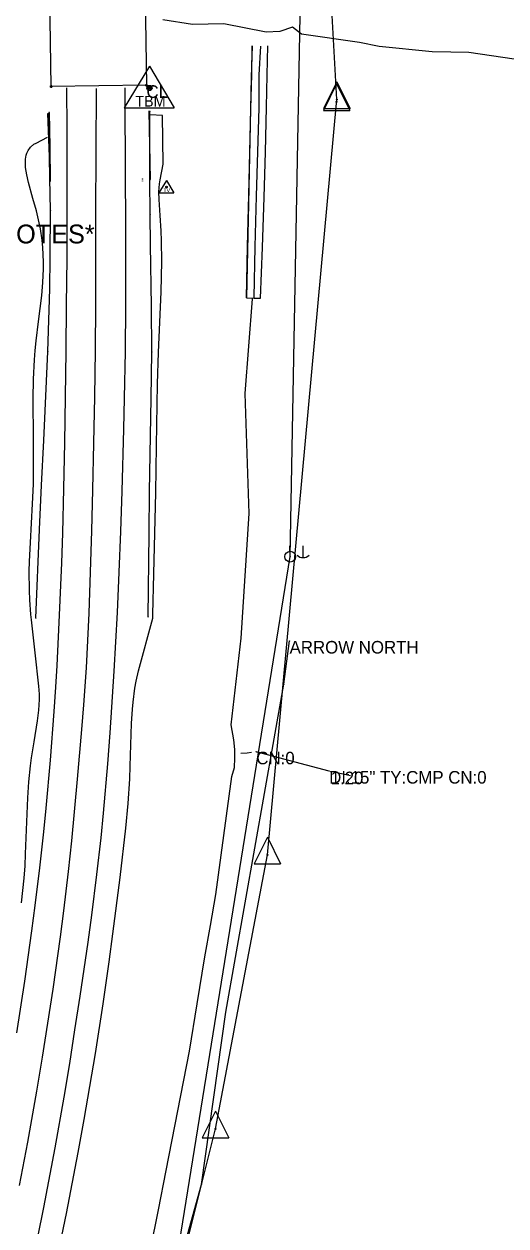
# Model space of a CAD drawing. Extents: x 1674300 to 1677920, y 225056 to 231852.
# Drawn here: x 1677431.2 to 1677622.7, y 228668.9 to 229147 of the extents above; entities that cross this region are included whole.
import ezdxf

# ---------------------------------------------------------------- set-up
doc = ezdxf.new("R2010")
doc.units = 0
for name, color, linetype in [('S_BRIDGE', 7, 'Continuous'), ('S_BRIDGE_ANNOT', 7, 'Continuous'), ('S_CAL_CORNER_ANNOT', 7, 'Continuous'), ('S_CURB', 7, 'Continuous'), ('S_DITCHLINE', 7, 'Continuous'), ('S_DRG_PT_SYM', 7, 'Continuous'), ('S_DROP_INLET_ANNOT', 7, 'Continuous'), ('S_EDGE_CONCRETE', 7, 'Continuous'), ('S_EDGE_PAVEMENT', 7, 'Continuous'), ('S_ELECTRIC_UTILITIES', 7, 'Continuous'), ('S_EXIST_ROW', 7, 'Continuous'), ('S_FIBER_OPTIC_CABLE', 7, 'Continuous'), ('S_FIBER_OPTIC_CABLE_ANNOT', 7, 'Continuous'), ('S_GUARDRAIL', 7, 'Continuous'), ('S_MSC_PT_SYM', 7, 'Continuous'), ('S_PAVEMENT_CROWN', 7, 'Continuous'), ('S_PRIMARY_CTL', 7, 'Continuous'), ('S_RDW_PT_SYM', 7, 'Continuous'), ('S_SECONDARY_CTL', 7, 'Continuous'), ('S_SHOULDER', 7, 'Continuous'), ('S_SIDE_DRAIN', 7, 'Continuous'), ('S_SIDE_DRAIN_ANNOT', 7, 'Continuous'), ('S_STR_PT_SYM', 7, 'Continuous'), ('S_STREAM', 7, 'Continuous'), ('S_UTILITY_POLE', 7, 'Continuous'), ('S_UTL_PT_SYM', 7, 'Continuous')]:
    doc.layers.add(name, color=color, linetype=linetype)

msp = doc.modelspace()

# ---------------------------------------------------------------- linework, layer by layer
at = {"layer": 'S_BRIDGE'}
for p, q in [((1677441.95, 229122.22), (1677441.12, 229176.97)), ((1677478.98, 229177.38), (1677479.86, 229122.68)), ((1677479.86, 229122.68), (1677441.95, 229122.22))]:
    msp.add_line(p, q, dxfattribs=at)
at = {"layer": 'S_CURB'}
msp.add_lwpolyline([(1677441.03, 229111.79), (1677441.26, 229098.22), (1677441.49, 229084.65), (1677441.72, 229084.58), (1677441.51, 229098.19), (1677441.3, 229111.8)], close=True, dxfattribs=at)
at = {"layer": 'S_DITCHLINE'}
for points in [[(1677522.63, 229038.26), (1677523.12, 229058.43), (1677523.6, 229078.59), (1677524.1, 229096.18), (1677524.6, 229113.77), (1677524.67, 229126.78), (1677525.27, 229138.2)], [(1677481.44, 228659.54), (1677484.58, 228675.24), (1677487.72, 228690.94), (1677492.32, 228714.69), (1677496.91, 228738.44), (1677499.97, 228757.22), (1677503.03, 228775.99), (1677505.25, 228788.38), (1677507.46, 228800.77), (1677510.6, 228824.19), (1677513.73, 228847.61), (1677514.83, 228851.31), (1677515.02, 228854.93), (1677514.96, 228858.41), (1677514.63, 228862.29), (1677513.48, 228868.18), (1677515.51, 228885.41), (1677517.54, 228902.65), (1677519.12, 228927.5), (1677520.71, 228952.35), (1677519.88, 228976.18), (1677519.06, 229000), (1677520.55, 229018.83), (1677522.04, 229037.67)], [(1677517.33, 228856.94), (1677519.88, 228857.15), (1677521.64, 228857.29)], [(1677561.01, 228848), (1677553.85, 228849.54)]]:
    msp.add_lwpolyline(points, dxfattribs=at)
at = {"layer": 'S_DRG_PT_SYM'}
for points in [[(1677523.52, 228857.52), (1677523.52, 228857.57), (1677523.52, 228857.52), (1677523.47, 228857.52), (1677523.52, 228857.52), (1677523.52, 228857.47), (1677523.52, 228857.52), (1677523.57, 228857.52)], [(1677552.48, 228849.85), (1677552.48, 228849.9), (1677552.48, 228849.85), (1677552.43, 228849.85), (1677552.48, 228849.85), (1677552.48, 228849.8), (1677552.48, 228849.85), (1677552.53, 228849.85)], [(1677553.05, 228849.61), (1677553.05, 228849.66), (1677553.05, 228849.61), (1677553, 228849.61), (1677553.05, 228849.61), (1677553.05, 228849.56), (1677553.05, 228849.61), (1677553.1, 228849.61)]]:
    msp.add_lwpolyline(points, dxfattribs=at)
at = {"layer": 'S_EDGE_CONCRETE'}
for points in [[(1677519.57, 229038.13), (1677520.04, 229058.54), (1677520.52, 229078.95), (1677520.93, 229096.11), (1677521.34, 229113.27), (1677521.67, 229126.86), (1677521.82, 229138.35), (1677521.53, 229125.82), (1677521.25, 229113.29), (1677520.97, 229100.76), (1677520.69, 229088.24), (1677520.41, 229075.71), (1677520.13, 229063.18), (1677519.85, 229050.65)], [(1677480.74, 229112.39), (1677481.01, 229098.81), (1677481.28, 229085.22), (1677481.44, 229085.19), (1677481.19, 229098.78), (1677480.94, 229112.36)]]:
    msp.add_lwpolyline(points, close=True, dxfattribs=at)
msp.add_lwpolyline([(1677519.58, 229038.11), (1677522.68, 229037.98), (1677525.2, 229037.96), (1677525.95, 229058.08), (1677526.69, 229078.2), (1677527.11, 229096.11), (1677527.53, 229114.03), (1677527.87, 229126.76), (1677528.09, 229138.32)], dxfattribs=at)
at = {"layer": 'S_EDGE_PAVEMENT'}
for points in [[(1677428.3, 228745.66), (1677431.48, 228766.31), (1677434.3, 228786.31), (1677435.61, 228796.33), (1677437.42, 228811.37), (1677438.99, 228825.61), (1677439.95, 228835.12), (1677441.69, 228854.14), (1677443.21, 228873.55), (1677443.86, 228883.26), (1677444.36, 228891.83), (1677445.2, 228908.97), (1677446.16, 228932.65), (1677446.57, 228944.49), (1677447.07, 228962.26), (1677447.45, 228980.47), (1677447.69, 228998.68), (1677447.94, 229016.89), (1677448.12, 229035.35), (1677448.29, 229053.8), (1677448.38, 229072.25), (1677448.38, 229088.73), (1677448.28, 229105.21), (1677448.18, 229121.69)], [(1677436.65, 228664.42), (1677439.04, 228676.26), (1677443.55, 228699.98), (1677447.09, 228720.05), (1677449.33, 228733.45), (1677451.44, 228746.87), (1677453.55, 228760.29), (1677456.69, 228781.76), (1677458.15, 228792.51), (1677460.17, 228808.65), (1677461.79, 228823.32), (1677462.77, 228833.1), (1677464.48, 228852.7), (1677465.41, 228864.99), (1677467.02, 228889.58), (1677468.3, 228912.92), (1677469.04, 228929.01), (1677469.62, 228945.1), (1677470.21, 228961.2), (1677470.9, 228985.89), (1677471.17, 228998.24), (1677471.46, 229016.76), (1677471.6, 229034.93), (1677471.6, 229053.1), (1677471.6, 229071.27), (1677471.53, 229083.86), (1677471.46, 229096.45), (1677471.39, 229109.03), (1677471.32, 229121.62)]]:
    msp.add_lwpolyline(points, dxfattribs=at)
at = {"layer": 'S_ELECTRIC_UTILITIES'}
for p, q in [((1677537.01, 228935.14), (1677541.67, 229188.26)), ((1677492.08, 228657.14), (1677537.01, 228935.14))]:
    msp.add_line(p, q, dxfattribs=at)
at = {"layer": 'S_EXIST_ROW'}
for p, q in [((1677555.5, 229117.02), (1677521.25, 229735.57)), ((1677555.45, 229123.25), (1677550.16, 229112.61)), ((1677555.52, 229124.11), (1677550.23, 229113.47)), ((1677555.45, 229123.25), (1677560.68, 229112.61)), ((1677555.52, 229124.11), (1677560.76, 229113.47)), ((1677527.92, 228816.46), (1677555.5, 229117.02)), ((1677555.43, 229116.15), (1677555.43, 229116.15)), ((1677555.5, 229117.02), (1677555.5, 229117.02)), ((1677550.16, 229112.61), (1677560.68, 229112.61)), ((1677550.23, 229113.47), (1677560.76, 229113.47)), ((1677527.94, 228823.55), (1677522.65, 228812.91)), ((1677527.94, 228823.55), (1677533.17, 228812.91)), ((1677507.28, 228707.44), (1677527.92, 228816.46)), ((1677527.92, 228816.46), (1677527.92, 228816.46)), ((1677522.65, 228812.91), (1677533.17, 228812.91)), ((1677507.3, 228714.54), (1677502.01, 228703.9)), ((1677507.3, 228714.54), (1677512.53, 228703.9)), ((1677453.53, 228492.88), (1677507.28, 228707.44)), ((1677507.28, 228707.44), (1677507.28, 228707.44)), ((1677502.01, 228703.9), (1677512.53, 228703.9))]:
    msp.add_line(p, q, dxfattribs=at)
for centre, radius in [((1677555.43, 229116.15), 0.18), ((1677555.5, 229117.02), 0.18), ((1677555.43, 229116.15), 0.09), ((1677555.5, 229117.02), 0.09), ((1677527.92, 228816.46), 0.18), ((1677527.92, 228816.46), 0.09), ((1677507.28, 228707.44), 0.18), ((1677507.28, 228707.44), 0.09)]:
    msp.add_circle(centre, radius, dxfattribs=at)
at = {"layer": 'S_FIBER_OPTIC_CABLE'}
for p, q in [((1677534.42, 228884.38), (1677536.75, 228901.6)), ((1677511.42, 228753.9), (1677534.42, 228884.38)), ((1677501.74, 228685.3), (1677511.42, 228753.9)), ((1677487.34, 228633.72), (1677501.74, 228685.3))]:
    msp.add_line(p, q, dxfattribs=at)
at = {"layer": 'S_GUARDRAIL'}
for p, q in [((1677441.28, 229094.28), (1677440.67, 229111.44)), ((1677481.21, 229085), (1677481.23, 229112.34)), ((1677441.49, 229085.7), (1677441.28, 229094.28)), ((1677441.66, 229072.83), (1677441.49, 229085.7)), ((1677481.3, 229071.32), (1677481.21, 229085)), ((1677441.63, 229054.13), (1677441.66, 229072.83)), ((1677481.45, 229059.15), (1677481.3, 229071.32)), ((1677481.81, 229034.81), (1677481.45, 229059.15)), ((1677441.44, 229041.66), (1677441.63, 229054.13)), ((1677441.24, 229033.35), (1677441.44, 229041.66)), ((1677481.93, 229016.55), (1677481.81, 229034.81)), ((1677440.69, 229016.73), (1677441.24, 229033.35)), ((1677440.18, 229004.92), (1677440.69, 229016.73)), ((1677481.78, 228998.05), (1677481.93, 229016.55)), ((1677439.02, 228981.3), (1677440.18, 229004.92)), ((1677481.09, 228961.05), (1677481.78, 228998.05)), ((1677438.13, 228963.59), (1677439.02, 228981.3)), ((1677437.33, 228945.95), (1677438.13, 228963.59)), ((1677480.86, 228944.41), (1677481.09, 228961.05)), ((1677435.91, 228910.66), (1677437.33, 228945.95)), ((1677480.54, 228911.14), (1677480.86, 228944.41))]:
    msp.add_line(p, q, dxfattribs=at)
at = {"layer": 'S_MSC_PT_SYM'}
for points in [[(1677535.79, 229145.03), (1677535.79, 229145.08), (1677535.79, 229145.03), (1677535.74, 229145.03), (1677535.79, 229145.03), (1677535.79, 229144.98), (1677535.79, 229145.03), (1677535.84, 229145.03)], [(1677478.28, 229084.57), (1677478.28, 229084.62), (1677478.28, 229084.57), (1677478.23, 229084.57), (1677478.28, 229084.57), (1677478.28, 229084.52), (1677478.28, 229084.57), (1677478.33, 229084.57)], [(1677478.29, 229085.42), (1677478.29, 229085.47), (1677478.29, 229085.42), (1677478.24, 229085.42), (1677478.29, 229085.42), (1677478.29, 229085.37), (1677478.29, 229085.42), (1677478.34, 229085.42)]]:
    msp.add_lwpolyline(points, dxfattribs=at)
at = {"layer": 'S_PAVEMENT_CROWN'}
msp.add_lwpolyline([(1677429.34, 228684.91), (1677432.69, 228702.16), (1677436.31, 228722.44), (1677438.56, 228735.98), (1677440.65, 228749.55), (1677442.74, 228763.12), (1677445.66, 228783.88), (1677447.01, 228794.27), (1677448.87, 228809.88), (1677450.17, 228822.13), (1677452.49, 228846.67), (1677454.21, 228866.32), (1677454.98, 228876.16), (1677455.99, 228890.92), (1677457.05, 228912.6), (1677457.66, 228928.98), (1677458.11, 228945.37), (1677458.57, 228961.75), (1677458.95, 228980.23), (1677459.33, 228998.7), (1677459.56, 229017.18), (1677459.66, 229035.28), (1677459.68, 229053.38), (1677459.71, 229071.47), (1677459.84, 229096.45), (1677459.96, 229121.43)], dxfattribs=at)
at = {"layer": 'S_PRIMARY_CTL'}
for p, q in [((1677481.03, 229130.28), (1677470.99, 229113.77)), ((1677481.03, 229130.28), (1677490.85, 229113.77)), ((1677470.99, 229113.77), (1677490.85, 229113.77))]:
    msp.add_line(p, q, dxfattribs=at)
for radius in [1.04, 0.609, 0.344]:
    msp.add_circle((1677481.03, 229121.58), radius, dxfattribs=at)
at = {"layer": 'S_RDW_PT_SYM'}
for points in [[(1677440.67, 229111.44), (1677440.67, 229111.49), (1677440.67, 229111.44), (1677440.62, 229111.44), (1677440.67, 229111.44), (1677440.67, 229111.39), (1677440.67, 229111.44), (1677440.72, 229111.44)], [(1677481.23, 229112.34), (1677481.23, 229112.39), (1677481.23, 229112.34), (1677481.18, 229112.34), (1677481.23, 229112.34), (1677481.23, 229112.29), (1677481.23, 229112.34), (1677481.28, 229112.34)], [(1677441.66, 229072.83), (1677441.66, 229072.88), (1677441.66, 229072.83), (1677441.61, 229072.83), (1677441.66, 229072.83), (1677441.66, 229072.78), (1677441.66, 229072.83), (1677441.71, 229072.83)], [(1677481.3, 229071.32), (1677481.3, 229071.37), (1677481.3, 229071.32), (1677481.25, 229071.32), (1677481.3, 229071.32), (1677481.3, 229071.27), (1677481.3, 229071.32), (1677481.35, 229071.32)], [(1677440.69, 229016.73), (1677440.69, 229016.78), (1677440.69, 229016.73), (1677440.64, 229016.73), (1677440.69, 229016.73), (1677440.69, 229016.68), (1677440.69, 229016.73), (1677440.74, 229016.73)], [(1677481.93, 229016.55), (1677481.93, 229016.6), (1677481.93, 229016.55), (1677481.88, 229016.55), (1677481.93, 229016.55), (1677481.93, 229016.5), (1677481.93, 229016.55), (1677481.98, 229016.55)], [(1677438.13, 228963.59), (1677438.13, 228963.64), (1677438.13, 228963.59), (1677438.08, 228963.59), (1677438.13, 228963.59), (1677438.13, 228963.54), (1677438.13, 228963.59), (1677438.18, 228963.59)], [(1677481.09, 228961.05), (1677481.09, 228961.1), (1677481.09, 228961.05), (1677481.04, 228961.05), (1677481.09, 228961.05), (1677481.09, 228961), (1677481.09, 228961.05), (1677481.14, 228961.05)], [(1677435.91, 228910.66), (1677435.91, 228910.71), (1677435.91, 228910.66), (1677435.86, 228910.66), (1677435.91, 228910.66), (1677435.91, 228910.61), (1677435.91, 228910.66), (1677435.96, 228910.66)], [(1677480.54, 228911.14), (1677480.54, 228911.19), (1677480.54, 228911.14), (1677480.49, 228911.14), (1677480.54, 228911.14), (1677480.54, 228911.09), (1677480.54, 228911.14), (1677480.59, 228911.14)]]:
    msp.add_lwpolyline(points, dxfattribs=at)
at = {"layer": 'S_SECONDARY_CTL'}
for p, q in [((1677487.81, 229084.79), (1677484.8, 229079.84)), ((1677487.81, 229084.79), (1677490.75, 229079.84)), ((1677484.8, 229079.84), (1677490.75, 229079.84))]:
    msp.add_line(p, q, dxfattribs=at)
for radius in [0.311, 0.183, 0.103]:
    msp.add_circle((1677487.81, 229082.18), radius, dxfattribs=at)
at = {"layer": 'S_SHOULDER'}
for points in [[(1677445.59, 228661.79), (1677448.04, 228673.87), (1677452.69, 228698.07), (1677455.02, 228711.19), (1677457.35, 228724.31), (1677459.53, 228737.45), (1677462.59, 228757.21), (1677464.98, 228773.94), (1677466.49, 228785.1), (1677469.34, 228807.44), (1677471.62, 228827.07), (1677472.53, 228836.91), (1677473.2, 228846.8), (1677473.42, 228851.77), (1677473.91, 228868.78), (1677474.26, 228874.41), (1677474.52, 228877.22), (1677475.26, 228882.78), (1677475.77, 228885.55), (1677476.72, 228889.65), (1677482.34, 228910.72), (1677482.37, 228912.13), (1677482.74, 228928.29), (1677483.05, 228939.06), (1677483.61, 228960.61), (1677483.9, 228979.19), (1677484.3, 229003.95), (1677484.68, 229016.32), (1677485.72, 229040.51), (1677485.97, 229052.63), (1677485.87, 229060.73), (1677485.72, 229064.79), (1677485.33, 229070.89), (1677484.86, 229077.21), (1677484.81, 229080.34), (1677485.03, 229083.45), (1677485.28, 229085), (1677486.51, 229091.31), (1677486.23, 229110.7), (1677481.28, 229110.91)], [(1677430.18, 228797.38), (1677431.2, 228807.23), (1677431.57, 228812.17), (1677431.83, 228816.92), (1677432.17, 228826.45), (1677432.64, 228839.16), (1677433.05, 228845.52), (1677433.69, 228851.87), (1677434.11, 228855.04), (1677435.17, 228861.4), (1677436.58, 228869.86), (1677437.06, 228874.09), (1677437.29, 228878.32), (1677437.27, 228880.43), (1677437.04, 228883.6), (1677435.59, 228896.81), (1677434.14, 228910.02), (1677433.92, 228912.18), (1677433.47, 228917.9), (1677433.32, 228921.72), (1677433.29, 228929.34), (1677433.38, 228933.16), (1677433.72, 228940.81), (1677434.59, 228956.19), (1677434.91, 228963.94), (1677435.01, 228969.95), (1677434.96, 228981.99), (1677434.83, 228997.92), (1677434.94, 229005.74), (1677435.29, 229013.42), (1677435.59, 229017.18), (1677435.99, 229021.07), (1677436.97, 229028.74), (1677438.26, 229039.01), (1677438.71, 229044.26), (1677438.93, 229049.66), (1677438.92, 229052.43), (1677438.64, 229058.12), (1677438.35, 229061.06), (1677437.68, 229065.6), (1677436.71, 229070.31), (1677436.11, 229072.74), (1677434.73, 229077.57), (1677432.93, 229083.99), (1677432.24, 229087.06), (1677431.82, 229089.97), (1677431.74, 229091.35), (1677431.8, 229093.29), (1677432.09, 229094.89), (1677432.32, 229095.63), (1677432.78, 229096.67), (1677433.76, 229098.06), (1677435.12, 229099.22), (1677435.96, 229099.7), (1677440.46, 229101.97)]]:
    msp.add_lwpolyline(points, dxfattribs=at)
at = {"layer": 'S_SIDE_DRAIN'}
msp.add_line((1677552.48, 228849.85), (1677523.52, 228857.52), dxfattribs=at)
at = {"layer": 'S_STR_PT_SYM'}
for points in [[(1677441.95, 229122.22), (1677441.95, 229122.72), (1677441.95, 229122.22), (1677441.45, 229122.22), (1677441.95, 229122.22), (1677441.95, 229121.72), (1677441.95, 229122.22), (1677442.45, 229122.22)], [(1677479.86, 229122.68), (1677479.86, 229123.18), (1677479.86, 229122.68), (1677479.36, 229122.68), (1677479.86, 229122.68), (1677479.86, 229122.18), (1677479.86, 229122.68), (1677480.36, 229122.68)]]:
    msp.add_lwpolyline(points, dxfattribs=at)
at = {"layer": 'S_STREAM'}
msp.add_lwpolyline([(1677626.04, 229133.07), (1677608, 229135.75), (1677600.84, 229135.91), (1677593.35, 229135.96), (1677572.37, 229138.06), (1677564.56, 229139.66), (1677541.46, 229143.03), (1677537.87, 229145.79), (1677532.82, 229144.1), (1677527.43, 229143.82), (1677510.66, 229147.15), (1677498.12, 229146.82), (1677486.33, 229148.7)], dxfattribs=at)
at = {"layer": 'S_UTILITY_POLE'}
for p, q in [((1677536.88, 228937.28), (1677536.88, 228939.39)), ((1677542.05, 228939.47), (1677542.05, 228934.74))]:
    msp.add_line(p, q, dxfattribs=at)
msp.add_circle((1677537.01, 228935.14), 2.13, dxfattribs=at)
msp.add_arc((1677542.11, 228938.17), 3.41, 226.3972, 313.6028, dxfattribs=at)
at = {"layer": 'S_UTL_PT_SYM'}
for points in [[(1677537.01, 228935.14), (1677537.01, 228935.19), (1677537.01, 228935.14), (1677536.96, 228935.14), (1677537.01, 228935.14), (1677537.01, 228935.09), (1677537.01, 228935.14), (1677537.06, 228935.14)], [(1677536.75, 228901.6), (1677536.75, 228901.65), (1677536.75, 228901.6), (1677536.7, 228901.6), (1677536.75, 228901.6), (1677536.75, 228901.55), (1677536.75, 228901.6), (1677536.8, 228901.6)], [(1677534.42, 228884.38), (1677534.42, 228884.43), (1677534.42, 228884.38), (1677534.37, 228884.38), (1677534.42, 228884.38), (1677534.42, 228884.33), (1677534.42, 228884.38), (1677534.47, 228884.38)], [(1677511.42, 228753.9), (1677511.42, 228753.95), (1677511.42, 228753.9), (1677511.37, 228753.9), (1677511.42, 228753.9), (1677511.42, 228753.85), (1677511.42, 228753.9), (1677511.47, 228753.9)], [(1677501.74, 228685.3), (1677501.74, 228685.35), (1677501.74, 228685.3), (1677501.69, 228685.3), (1677501.74, 228685.3), (1677501.74, 228685.25), (1677501.74, 228685.3), (1677501.79, 228685.3)]]:
    msp.add_lwpolyline(points, dxfattribs=at)

# ---------------------------------------------------------------- texts
at = {"layer": 'S_BRIDGE_ANNOT'}
msp.add_text('CL', height=5, rotation=360, dxfattribs=at).set_placement((1677479.86, 229117.68))
at = {"layer": 'S_CAL_CORNER_ANNOT'}
msp.add_text('*SEE CORNER NOTES*', height=7.5, rotation=360, dxfattribs=at).set_placement((1677347.8, 229059.76))
at = {"layer": 'S_DROP_INLET_ANNOT'}
msp.add_text('1.20', height=5, rotation=360, dxfattribs=at).set_placement((1677553.05, 228844.61))
at = {"layer": 'S_FIBER_OPTIC_CABLE_ANNOT'}
msp.add_text('ARROW NORTH', height=5, rotation=360, dxfattribs=at).set_placement((1677536.75, 228896.6))
at = {"layer": 'S_PRIMARY_CTL'}
msp.add_text('TBM', height=4.287, rotation=360, dxfattribs=at).set_placement((1677475.37, 229114.19))
at = {"layer": 'S_SECONDARY_CTL'}
msp.add_text('TV', height=1.5, rotation=360, dxfattribs=at).set_placement((1677486.6, 229080.17))
at = {"layer": 'S_SIDE_DRAIN_ANNOT'}
for s, p in [('CN:0', (1677523.52, 228852.52)), ('DI:15" TY:CMP CN:0', (1677552.48, 228844.85))]:
    msp.add_text(s, height=5, rotation=360, dxfattribs=at).set_placement(p)

doc.saveas('drawing.dxf')
